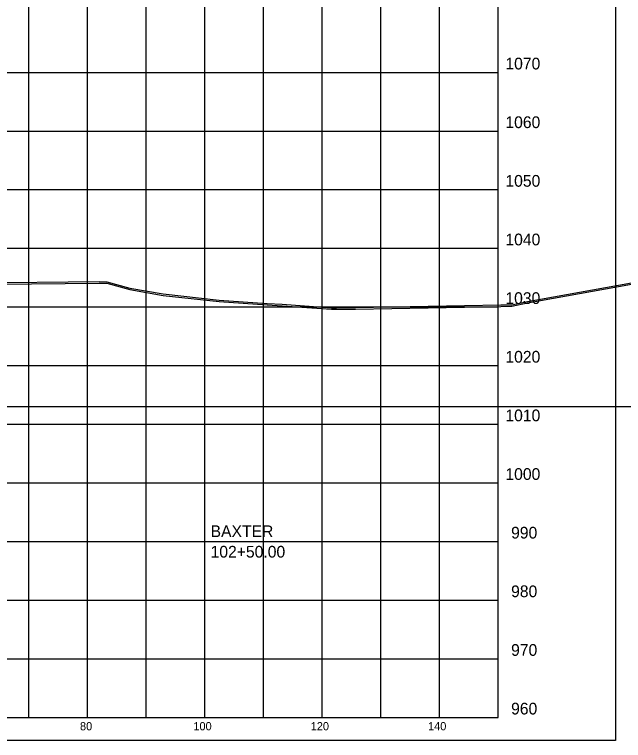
# Model space of a CAD drawing. Extents: x 5868 to 6683, y 2883 to 19120.
# Drawn here: x 6261.4 to 6365.2, y 5388.1 to 5511.9 of the extents above; entities that cross this region are included whole.
import ezdxf

# ---------------------------------------------------------------- set-up
doc = ezdxf.new("R2010")
doc.units = 0
for name, color, linetype in [('DESIGN - SHEET - Corner Text', 7, 'Continuous'), ('DESIGN - SHEET - Light Grid', 7, 'Continuous'), ('DESIGN - SHEET - Linework', 7, 'Continuous'), ('DESIGN - SHEET - Plot Shape', 7, 'Continuous'), ('DESIGN - TYPICAL - Warning Text', 7, 'Continuous'), ('SURVEY - GROUND - Bottom of Topsoil Layer', 7, 'Continuous'), ('SURVEY - GROUND - Top of Ground', 7, 'Continuous')]:
    doc.layers.add(name, color=color, linetype=linetype)

msp = doc.modelspace()

# ---------------------------------------------------------------- linework, layer by layer
at = {"layer": 'DESIGN - SHEET - Light Grid'}
msp.add_line((6193.78, 5445.07), (6493.78, 5445.07), dxfattribs=at)
at = {"layer": 'DESIGN - SHEET - Linework'}
for p, q in [((6263.78, 5392.07), (6263.78, 5602.07)), ((6273.78, 5392.07), (6273.78, 5602.07)), ((6283.78, 5392.07), (6283.78, 5602.07)), ((6293.78, 5392.07), (6293.78, 5602.07)), ((6303.78, 5392.07), (6303.78, 5602.07)), ((6313.78, 5392.07), (6313.78, 5602.07)), ((6323.78, 5392.07), (6323.78, 5602.07)), ((6333.78, 5392.07), (6333.78, 5602.07)), ((6043.78, 5502.07), (6343.78, 5502.07)), ((6043.78, 5492.07), (6343.78, 5492.07)), ((6043.78, 5482.07), (6343.78, 5482.07)), ((6043.78, 5472.07), (6343.78, 5472.07)), ((6043.78, 5462.07), (6343.78, 5462.07)), ((6043.78, 5452.07), (6343.78, 5452.07)), ((6043.78, 5442.07), (6343.78, 5442.07)), ((6043.78, 5432.07), (6343.78, 5432.07)), ((6043.78, 5422.07), (6343.78, 5422.07)), ((6043.78, 5412.07), (6343.78, 5412.07)), ((6043.78, 5402.07), (6343.78, 5402.07))]:
    msp.add_line(p, q, dxfattribs=at)
msp.add_lwpolyline([(6043.78, 5602.07), (6043.78, 5392.07), (6343.78, 5392.07), (6343.78, 5602.07)], dxfattribs=at)
at = {"layer": 'DESIGN - SHEET - Plot Shape'}
msp.add_lwpolyline([(6023.78, 5606.01), (6363.78, 5606.01), (6363.78, 5388.13), (6023.78, 5388.13)], close=True, dxfattribs=at)
at = {"layer": 'SURVEY - GROUND - Bottom of Topsoil Layer'}
for p, q in [((6254.51, 5465.94), (6275.78, 5466.13)), ((6275.78, 5466.13), (6277.11, 5466.1)), ((6277.11, 5466.1), (6281, 5465.03)), ((6348.81, 5462.74), (6366.53, 5465.93)), ((6281, 5465.03), (6286.67, 5464.03)), ((6286.67, 5464.03), (6296.24, 5462.98)), ((6296.24, 5462.98), (6304.42, 5462.4)), ((6304.42, 5462.4), (6306.99, 5462.28)), ((6306.99, 5462.28), (6315.39, 5461.66)), ((6346.13, 5462.19), (6348.81, 5462.74)), ((6315.39, 5461.66), (6315.86, 5461.68)), ((6315.86, 5461.68), (6316.24, 5461.68)), ((6316.24, 5461.68), (6319.47, 5461.7)), ((6319.47, 5461.7), (6344.24, 5462.17)), ((6344.24, 5462.17), (6346.13, 5462.19))]:
    msp.add_line(p, q, dxfattribs=at)
at = {"layer": 'SURVEY - GROUND - Top of Ground'}
msp.add_lwpolyline([(6254.51, 5466.19), (6275.78, 5466.38), (6277.11, 5466.35), (6281, 5465.28), (6286.67, 5464.28), (6296.24, 5463.23), (6304.42, 5462.65), (6306.99, 5462.53), (6315.39, 5461.91), (6315.86, 5461.93), (6316.24, 5461.93), (6319.47, 5461.95), (6344.24, 5462.42), (6346.13, 5462.44), (6348.81, 5462.99), (6366.53, 5466.18)], dxfattribs=at)

# ---------------------------------------------------------------- texts
at = {"layer": 'DESIGN - SHEET - Corner Text'}
for s, height, p in [('1070', 2, (6345.03, 5502.57)), ('1060', 2, (6345.03, 5492.57)), ('1050', 2, (6345.03, 5482.57)), ('1040', 2, (6345.03, 5472.57)), ('1030', 2, (6345.03, 5462.57)), ('1020', 2, (6345.03, 5452.57)), ('1010', 2, (6345.03, 5442.57)), ('1000', 2, (6345.03, 5432.57)), ('990', 2, (6346, 5422.57)), ('980', 2, (6346, 5412.57)), ('970', 2, (6346, 5402.57)), ('960', 2, (6346, 5392.57)), ('80', 1.4, (6272.52, 5389.87)), ('100', 1.4, (6291.84, 5389.87)), ('120', 1.4, (6311.84, 5389.87)), ('140', 1.4, (6331.84, 5389.87))]:
    msp.add_text(s, height=height, dxfattribs=at).set_placement(p)
at = {"layer": 'DESIGN - TYPICAL - Warning Text'}
for s, p in [('BAXTER', (6294.78, 5422.82)), ('102+50.00', (6294.78, 5419.32))]:
    msp.add_text(s, height=2, dxfattribs=at).set_placement(p)

doc.saveas('drawing.dxf')
